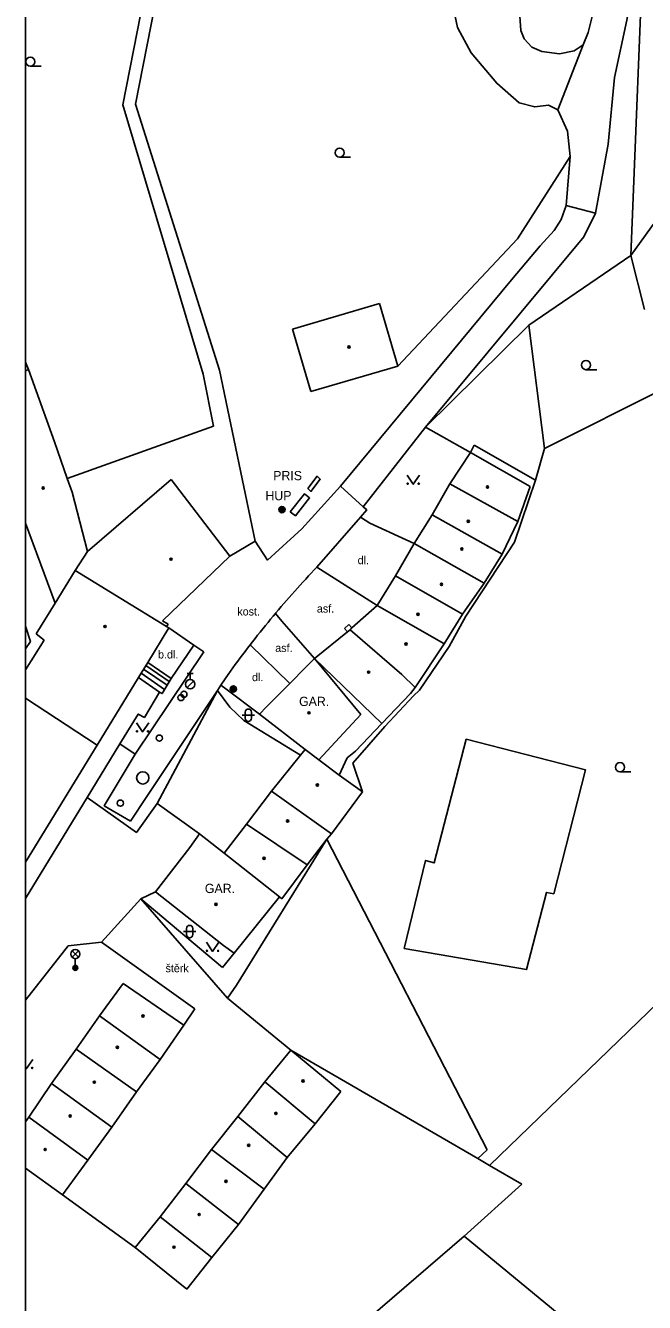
# Model space of a CAD drawing. Extents: x -598233 to -596890, y -1157848 to -1156431.
# Drawn here: x -598232.9 to -598182.6, y -1156791.2 to -1156687.5 of the extents above; entities that cross this region are included whole.
import ezdxf

# ---------------------------------------------------------------- set-up
doc = ezdxf.new("R2010")
doc.units = 0
for name, color, linetype in [('Level 10', 7, 'Continuous'), ('Level 11', 7, 'Continuous'), ('Level 24', 7, 'Continuous'), ('Level 25', 7, 'Continuous'), ('Level 27', 7, 'Continuous'), ('Level 28', 7, 'Continuous'), ('Level 33', 7, 'Continuous'), ('Level 36', 7, 'Continuous'), ('Level 39', 7, 'Continuous'), ('Level 40', 7, 'Continuous'), ('Level 41', 7, 'Continuous'), ('Level 5', 7, 'Continuous'), ('Level 51', 7, 'Continuous'), ('Level 8', 7, 'Continuous'), ('Vrstva 60', 7, 'Continuous'), ('zajmove_uzemi', 7, 'Continuous')]:
    doc.layers.add(name, color=color, linetype=linetype)

msp = doc.modelspace()

# ---------------------------------------------------------------- linework, layer by layer
at = {"layer": 'Level 10'}
for p, q in [((-598232.8901, -1156758.434), (-598227.88, -1156750.2199)), ((-598229.42, -1156762.27), (-598232.8901, -1156766.6794))]:
    msp.add_line(p, q, dxfattribs=at)
for points in [[(-598214.24, -1156729.4), (-598213.23, -1156730.95), (-598210.46, -1156728.4099), (-598207.31, -1156724.94)], [(-598205.46, -1156726.62), (-598207.31, -1156724.94)], [(-598209.23, -1156731.51), (-598205.7, -1156727.45), (-598205.18, -1156726.87), (-598205.46, -1156726.62)], [(-598209.69, -1156732), (-598209.91, -1156732.24), (-598210.14, -1156732.49)], [(-598209.69, -1156732), (-598209.46, -1156731.75), (-598209.23, -1156731.51)], [(-598216.69, -1156740.6), (-598216.44, -1156740.25), (-598216.25, -1156739.98), (-598216.05, -1156739.71), (-598215.86, -1156739.44), (-598215.66, -1156739.17), (-598215.46, -1156738.9), (-598215.26, -1156738.63), (-598215.06, -1156738.37), (-598214.86, -1156738.1), (-598214.65, -1156737.84), (-598214.45, -1156737.58), (-598214.24, -1156737.31), (-598214.04, -1156737.05), (-598213.83, -1156736.79), (-598213.62, -1156736.53), (-598213.41, -1156736.27), (-598213.2, -1156736.01), (-598212.99, -1156735.76), (-598212.77, -1156735.5), (-598212.6, -1156735.3), (-598212.56, -1156735.24), (-598212.35, -1156734.99), (-598212.13, -1156734.73), (-598211.91, -1156734.48), (-598211.69, -1156734.23), (-598211.48, -1156733.98), (-598211.26, -1156733.73), (-598211.03, -1156733.48), (-598210.81, -1156733.23), (-598210.59, -1156732.98), (-598210.37, -1156732.73), (-598210.14, -1156732.49)], [(-598218.42, -1156738.4), (-598223.98, -1156746.7), (-598225.23, -1156745.87)], [(-598217.29, -1156741.54), (-598217.02, -1156741.12), (-598216.69, -1156740.6)], [(-598223.04, -1156750.16), (-598217.29, -1156741.54)], [(-598227.88, -1156750.2199), (-598225.23, -1156745.87)], [(-598222.34, -1156757.89), (-598223.53, -1156758.46)], [(-598226.71, -1156761.9699), (-598223.53, -1156758.46)], [(-598229.42, -1156762.27), (-598226.71, -1156761.9699)]]:
    msp.add_lwpolyline(points, dxfattribs=at)
at = {"layer": 'Level 11'}
for p, q in [((-598232.8901, -1156736.323), (-598232.5, -1156737.55)), ((-598232.5, -1156737.55), (-598232.8901, -1156738.1619))]:
    msp.add_line(p, q, dxfattribs=at)
for points in [[(-598184.68, -1156671.86), (-598186.69, -1156686.03), (-598187.2, -1156688.09), (-598187.6, -1156689.09), (-598188.35, -1156689.6), (-598189.54, -1156689.84), (-598190.96, -1156689.65), (-598191.77, -1156689.29), (-598192.4, -1156688.61), (-598192.68, -1156687.94), (-598192.81, -1156685.99)], [(-598186.61, -1156702.76), (-598185.58, -1156697.18), (-598185.06, -1156691.75), (-598184.07, -1156687.1), (-598182.64, -1156678.57)], [(-598198.22, -1156685.76), (-598197.8, -1156687.7), (-598196.69, -1156689.76), (-598194.62, -1156692.22), (-598192.8, -1156693.81), (-598191.54, -1156694.15), (-598190.42, -1156694.01), (-598189.66, -1156694.37), (-598188.87, -1156696.11), (-598188.67, -1156698.18), (-598188.98, -1156702.16)], [(-598189.66, -1156694.37), (-598187.6, -1156689.09)], [(-598192.93, -1156704.87), (-598188.67, -1156698.18)], [(-598207.31, -1156724.94), (-598193.44, -1156708.18), (-598191.1, -1156705.43), (-598189.95, -1156704.17), (-598189.39, -1156703.28), (-598188.98, -1156702.16)], [(-598186.61, -1156702.76), (-598187.54, -1156704.69), (-598200.42, -1156720.14), (-598205.46, -1156726.62)], [(-598188.98, -1156702.16), (-598186.61, -1156702.76)], [(-598196.4699, -1156721.62), (-598196.75, -1156722.2)], [(-598191.4699, -1156724.45), (-598196.4699, -1156721.62)], [(-598191.4699, -1156724.45), (-598190.75, -1156721.89)], [(-598193.19, -1156729.48), (-598191.4699, -1156724.45)], [(-598205.7, -1156727.45), (-598204.93, -1156727.96)], [(-598201.33, -1156729.59), (-598204.93, -1156727.96)], [(-598197.14, -1156735.49), (-598193.19, -1156729.48)], [(-598204.33, -1156734.65), (-598209.23, -1156731.51)], [(-598212.07, -1156735.9), (-598212.6, -1156735.3)], [(-598209.43, -1156738.94), (-598212.07, -1156735.9)], [(-598198.49, -1156737.98), (-598197.14, -1156735.49)], [(-598221.26, -1156736.45), (-598219.2199, -1156737.85)], [(-598219.2199, -1156737.85), (-598221.07, -1156740.56)], [(-598219.2199, -1156737.85), (-598218.42, -1156738.4)], [(-598214.65, -1156737.84), (-598211.44, -1156740.97)], [(-598200.9099, -1156741.51), (-598198.49, -1156737.98)], [(-598222.9699, -1156739.26), (-598221.07, -1156740.56)], [(-598223.51, -1156740.14), (-598221.6, -1156741.45)], [(-598221.39, -1156741.1), (-598223.3, -1156739.8)], [(-598223.13, -1156739.52), (-598221.23, -1156740.82)], [(-598222, -1156741.67), (-598223.7199, -1156740.48)], [(-598221.07, -1156740.56), (-598221.8, -1156741.79), (-598222, -1156741.67)], [(-598216.63, -1156741.4), (-598217.02, -1156741.12)], [(-598217.29, -1156741.54), (-598222.19, -1156750.71), (-598223.88, -1156753.07), (-598227.88, -1156750.22)], [(-598222, -1156741.67), (-598223.24, -1156743.7199), (-598223.74, -1156743.45), (-598225.23, -1156745.87)], [(-598217.29, -1156741.54), (-598216.29, -1156742.89), (-598215.17, -1156743.9699), (-598210.57, -1156746.8)], [(-598213.89, -1156743.46), (-598216.63, -1156741.4)], [(-598203.7199, -1156744.46), (-598201.38, -1156741.98)], [(-598201.38, -1156741.98), (-598200.9099, -1156741.51)], [(-598206.32, -1156747.44), (-598203.7199, -1156744.46)], [(-598203.96, -1156744.23), (-598206.09, -1156746.46)], [(-598197.12, -1156745.48), (-598187.41, -1156747.99), (-598190, -1156758.05), (-598190.59, -1156757.94), (-598192.21, -1156764.21), (-598202.13, -1156762.49), (-598200.41, -1156755.34), (-598199.72, -1156755.54), (-598197.12, -1156745.48)], [(-598206.09, -1156746.46), (-598206.77, -1156747)], [(-598223.98, -1156746.7), (-598226.5, -1156750.9), (-598224.38, -1156752.16)], [(-598206.77, -1156747), (-598207.4099, -1156748.4099)], [(-598205.52, -1156749.76), (-598206.32, -1156747.44)], [(-598223.04, -1156750.16), (-598224.38, -1156752.16)], [(-598218.76, -1156753.17), (-598222.19, -1156750.71)], [(-598215.76, -1156765.48), (-598208.4099, -1156753.61)], [(-598223.53, -1156758.46), (-598216.89, -1156764.03)], [(-598216.48, -1156766.53), (-598223.53, -1156758.46)], [(-598226.71, -1156761.9699), (-598219.13, -1156767.4)], [(-598216.89, -1156764.03), (-598215.95, -1156762.86)], [(-598216.48, -1156766.53), (-598215.76, -1156765.48)], [(-598211.35, -1156770.76), (-598216.48, -1156766.53)], [(-598219.13, -1156767.4), (-598220.03, -1156768.71)], [(-598229.89, -1156782.5), (-598224, -1156786.77)]]:
    msp.add_lwpolyline(points, dxfattribs=at)
at = {"layer": 'Level 24'}
for points in [[(-598209.96, -1156725.13), (-598209.21, -1156724.14), (-598208.96, -1156724.39), (-598209.71, -1156725.37), (-598209.96, -1156725.13)], [(-598211.4, -1156727.02), (-598210.24, -1156725.58), (-598209.82, -1156725.9), (-598210.98, -1156727.35), (-598211.4, -1156727.02)], [(-598207, -1156736.5), (-598206.65, -1156736.17)], [(-598206.38, -1156736.46), (-598206.65, -1156736.17)], [(-598206.74, -1156736.77), (-598207, -1156736.5)]]:
    msp.add_lwpolyline(points, dxfattribs=at)
at = {"layer": 'Level 25'}
for centre, radius in [((-598212.07, -1156726.85), 0.25), ((-598212.07, -1156726.85), 0.2), ((-598212.07, -1156726.85), 0.15), ((-598212.07, -1156726.85), 0.1), ((-598212.07, -1156726.85), 0.05), ((-598216.01, -1156741.42), 0.25), ((-598216.01, -1156741.42), 0.2), ((-598216.01, -1156741.42), 0.15), ((-598216.01, -1156741.42), 0.1), ((-598216.01, -1156741.42), 0.05)]:
    msp.add_circle(centre, radius, dxfattribs=at)
at = {"layer": 'Level 27'}
msp.add_circle((-598223.37, -1156748.64), 0.5, dxfattribs=at)
at = {"layer": 'Level 28'}
for p, q in [((-598219.77, -1156740.155), (-598219.27, -1156740.155)), ((-598219.52, -1156740.655), (-598219.52, -1156740.155)), ((-598219.778, -1156741.302), (-598219.248, -1156740.772))]:
    msp.add_line(p, q, dxfattribs=at)
for centre, radius in [((-598219.52, -1156741.03), 0.375), ((-598220.27, -1156742.11), 0.25), ((-598220.03, -1156741.84), 0.25), ((-598222.02, -1156745.4099), 0.25), ((-598225.19, -1156750.69), 0.25)]:
    msp.add_circle(centre, radius, dxfattribs=at)
at = {"layer": 'Level 33'}
for p, q in [((-598229.115, -1156763.21), (-598228.585, -1156762.68)), ((-598229.115, -1156762.68), (-598228.585, -1156763.21)), ((-598228.85, -1156763.32), (-598228.85, -1156764.07))]:
    msp.add_line(p, q, dxfattribs=at)
for centre, radius in [((-598228.85, -1156762.945), 0.375), ((-598228.85, -1156764.07), 0.2), ((-598228.85, -1156764.07), 0.1445), ((-598228.85, -1156764.07), 0.0876)]:
    msp.add_circle(centre, radius, dxfattribs=at)
at = {"layer": 'Level 36'}
for p, q in [((-598232.5, -1156690.8449), (-598231.625, -1156690.8449)), ((-598207.38, -1156698.235), (-598206.505, -1156698.235)), ((-598187.38, -1156715.485), (-598186.505, -1156715.485)), ((-598215.046, -1156743.296), (-598215.046, -1156743.796)), ((-598214.546, -1156743.296), (-598214.546, -1156743.796)), ((-598215.296, -1156743.546), (-598214.296, -1156743.546)), ((-598184.62, -1156748.145), (-598183.745, -1156748.145)), ((-598219.806, -1156760.866), (-598219.806, -1156761.366)), ((-598219.306, -1156760.866), (-598219.306, -1156761.366)), ((-598220.056, -1156761.116), (-598219.056, -1156761.116))]:
    msp.add_line(p, q, dxfattribs=at)
for points in [[(-598201.91, -1156724.04), (-598201.41, -1156724.79), (-598200.91, -1156724.04)], [(-598223.89, -1156744.1599), (-598223.39, -1156744.9099), (-598222.89, -1156744.1599)], [(-598218.2, -1156761.98), (-598217.7, -1156762.73), (-598217.2, -1156761.98)], [(-598232.8901, -1156772.1149), (-598232.8, -1156772.25), (-598232.3, -1156771.5)]]:
    msp.add_lwpolyline(points, dxfattribs=at)
for centre, radius in [((-598232.5001, -1156690.4698), 0.375), ((-598207.3801, -1156697.8599), 0.375), ((-598187.3801, -1156715.1099), 0.375), ((-598201.8602, -1156724.7398), 0.05), ((-598200.9608, -1156724.7398), 0.05), ((-598223.8402, -1156744.8597), 0.05), ((-598222.9408, -1156744.8597), 0.05), ((-598184.6201, -1156747.7699), 0.375), ((-598218.1502, -1156762.6798), 0.05), ((-598217.2508, -1156762.6798), 0.05), ((-598232.3508, -1156772.1998), 0.05)]:
    msp.add_circle(centre, radius, dxfattribs=at)
for centre, start, end in [((-598214.7957, -1156743.2963), 0, 180), ((-598214.7957, -1156743.7963), 180, 0), ((-598219.5557, -1156760.8663), 0, 180), ((-598219.5557, -1156761.3663), 180, 0)]:
    msp.add_arc(centre, 0.25, start, end, dxfattribs=at)
at = {"layer": 'Level 39'}
for centre, radius in [((-598206.63, -1156713.64), 0.09), ((-598206.63, -1156713.64), 0.0398), ((-598231.46, -1156725.09), 0.09), ((-598231.46, -1156725.09), 0.0398), ((-598195.38, -1156725.01), 0.09), ((-598195.38, -1156725.01), 0.0398), ((-598196.94, -1156727.8), 0.09), ((-598196.94, -1156727.8), 0.0398), ((-598197.46, -1156730.05), 0.09), ((-598221.07, -1156730.87), 0.09), ((-598221.07, -1156730.87), 0.0398), ((-598197.46, -1156730.05), 0.0398), ((-598199.11, -1156732.92), 0.09), ((-598199.11, -1156732.92), 0.0398), ((-598201.02, -1156735.35), 0.09), ((-598201.02, -1156735.35), 0.0398), ((-598226.43, -1156736.34), 0.09), ((-598226.43, -1156736.34), 0.0398), ((-598201.99, -1156737.77), 0.09), ((-598201.99, -1156737.77), 0.0398), ((-598205.03, -1156740.05), 0.09), ((-598205.03, -1156740.05), 0.0398), ((-598209.87, -1156743.35), 0.09), ((-598209.87, -1156743.35), 0.0398), ((-598209.19, -1156749.2199), 0.09), ((-598209.19, -1156749.2199), 0.0398), ((-598211.61, -1156752.13), 0.09), ((-598211.61, -1156752.13), 0.0398), ((-598213.52, -1156755.17), 0.09), ((-598213.52, -1156755.17), 0.0398), ((-598217.43, -1156758.9099), 0.09), ((-598217.43, -1156758.9099), 0.0398), ((-598223.35, -1156767.98), 0.09), ((-598223.35, -1156767.98), 0.0398), ((-598225.43, -1156770.52), 0.09), ((-598225.43, -1156770.52), 0.0398), ((-598227.3, -1156773.35), 0.09), ((-598227.3, -1156773.35), 0.0398), ((-598210.35, -1156773.25), 0.09), ((-598210.35, -1156773.25), 0.0398), ((-598229.27, -1156776.1), 0.09), ((-598229.27, -1156776.1), 0.0398), ((-598212.56, -1156775.89), 0.09), ((-598212.56, -1156775.89), 0.0398), ((-598214.77, -1156778.48), 0.09), ((-598214.77, -1156778.48), 0.0398), ((-598231.3, -1156778.82), 0.09), ((-598231.3, -1156778.82), 0.0398), ((-598216.61, -1156781.4099), 0.09), ((-598216.61, -1156781.4099), 0.0398), ((-598218.79, -1156784.1), 0.09), ((-598218.79, -1156784.1), 0.0398), ((-598220.84, -1156786.75), 0.09), ((-598220.84, -1156786.75), 0.0398)]:
    msp.add_circle(centre, radius, dxfattribs=at)
at = {"layer": 'Level 5'}
for p, q in [((-598232.8901, -1156715.5829), (-598232.6599, -1156715.48)), ((-598232.8901, -1156727.9444), (-598230.48, -1156734.44)), ((-598232.8901, -1156739.8554), (-598231.38, -1156737.45)), ((-598232.8901, -1156742.151), (-598227.07, -1156745.98)), ((-598227.07, -1156745.98), (-598232.8901, -1156755.4825)), ((-598232.8901, -1156776.5748), (-598232.61, -1156776.18)), ((-598229.89, -1156782.5), (-598232.8901, -1156780.3427))]:
    msp.add_line(p, q, dxfattribs=at)
for points in [[(-598211.2199, -1156712.2), (-598204.14, -1156710.12)], [(-598204.14, -1156710.12), (-598202.65, -1156715.19)], [(-598209.73, -1156717.27), (-598211.2199, -1156712.2)], [(-598202.65, -1156715.19), (-598209.73, -1156717.27)], [(-598230.54, -1156721.35), (-598232.6599, -1156715.48)], [(-598229.5, -1156724.32), (-598230.54, -1156721.35)], [(-598198.43, -1156724.75), (-598196.75, -1156722.2)], [(-598196.75, -1156722.2), (-598191.9, -1156724.98)], [(-598229.11, -1156725.43), (-598229.5, -1156724.32)], [(-598227.86, -1156730.25), (-598221.07, -1156724.4)], [(-598221.07, -1156724.4), (-598216.3, -1156730.63)], [(-598199.88, -1156727.26), (-598198.43, -1156724.75)], [(-598198.43, -1156724.75), (-598192.9099, -1156727.81)], [(-598229.11, -1156725.43), (-598227.86, -1156730.25)], [(-598191.9, -1156724.98), (-598192.9099, -1156727.81)], [(-598201.33, -1156729.59), (-598199.88, -1156727.26)], [(-598199.88, -1156727.26), (-598194.19, -1156730.46)], [(-598192.9099, -1156727.81), (-598194.19, -1156730.46)], [(-598202.84, -1156732.24), (-598201.33, -1156729.59)], [(-598201.33, -1156729.59), (-598195.65, -1156732.81)], [(-598227.86, -1156730.25), (-598228.86, -1156731.8)], [(-598221.76, -1156735.88), (-598216.3, -1156730.63)], [(-598194.19, -1156730.46), (-598195.65, -1156732.81)], [(-598230.48, -1156734.44), (-598228.86, -1156731.8)], [(-598228.86, -1156731.8), (-598221.43, -1156736.34)], [(-598202.84, -1156732.24), (-598204.33, -1156734.65)], [(-598197.4, -1156735.33), (-598202.84, -1156732.24)], [(-598195.65, -1156732.81), (-598197.4, -1156735.33)], [(-598232.03, -1156736.94), (-598230.48, -1156734.44)], [(-598206.53, -1156736.6), (-598206.38, -1156736.46), (-598204.33, -1156734.65)], [(-598204.33, -1156734.65), (-598199.11, -1156737.62)], [(-598221.3, -1156736.1599), (-598221.76, -1156735.88)], [(-598221.3, -1156736.1599), (-598221.43, -1156736.34)], [(-598198.89, -1156737.75), (-598197.4, -1156735.33)], [(-598231.38, -1156737.45), (-598232.03, -1156736.94)], [(-598221.26, -1156736.45), (-598222.9699, -1156739.26)], [(-598221.43, -1156736.34), (-598221.26, -1156736.45)], [(-598209.43, -1156738.94), (-598206.74, -1156736.77), (-598206.53, -1156736.6)], [(-598206.53, -1156736.6), (-598202.34, -1156740.24)], [(-598198.89, -1156737.75), (-598201.24, -1156741.29)], [(-598199.11, -1156737.62), (-598198.89, -1156737.75)], [(-598222.9699, -1156739.26), (-598223.7199, -1156740.48)], [(-598210.12, -1156739.64), (-598209.43, -1156738.94)], [(-598203.96, -1156744.23), (-598209.43, -1156738.94)], [(-598209.43, -1156738.94), (-598205.6599, -1156743.49)], [(-598211.9699, -1156741.51), (-598211.44, -1156740.97), (-598210.12, -1156739.64)], [(-598202.34, -1156740.24), (-598201.24, -1156741.29)], [(-598223.7199, -1156740.48), (-598227.07, -1156745.98)], [(-598201.24, -1156741.29), (-598201.63, -1156741.79)], [(-598213.31, -1156742.87), (-598211.9699, -1156741.51)], [(-598201.63, -1156741.79), (-598203.96, -1156744.23)], [(-598213.89, -1156743.46), (-598213.31, -1156742.87)], [(-598210.19, -1156746.33), (-598213.89, -1156743.46)], [(-598205.6599, -1156743.49), (-598207.39, -1156745.36)], [(-598207.39, -1156745.36), (-598209.06, -1156747.17)], [(-598210.57, -1156746.8), (-598210.19, -1156746.33)], [(-598210.19, -1156746.33), (-598209.06, -1156747.17)], [(-598212.93, -1156749.71), (-598210.57, -1156746.8)], [(-598209.06, -1156747.17), (-598207.4099, -1156748.4099)], [(-598207.4099, -1156748.4099), (-598205.52, -1156749.76)], [(-598214.95, -1156752.39), (-598212.93, -1156749.71)], [(-598208.05, -1156753.18), (-598212.93, -1156749.71)], [(-598205.52, -1156749.76), (-598208.05, -1156753.18)], [(-598216.77, -1156754.75), (-598214.95, -1156752.39)], [(-598210.02, -1156755.69), (-598214.95, -1156752.39)], [(-598218.76, -1156753.17), (-598219.56, -1156754.28)], [(-598216.77, -1156754.75), (-598218.76, -1156753.17)], [(-598208.4099, -1156753.61), (-598210.02, -1156755.69)], [(-598208.05, -1156753.18), (-598208.4099, -1156753.61)], [(-598219.56, -1156754.28), (-598222.34, -1156757.89)], [(-598212.26, -1156758.31), (-598216.77, -1156754.75)], [(-598210.02, -1156755.69), (-598212.08, -1156758.45)], [(-598222.34, -1156757.89), (-598216.81, -1156762.24)], [(-598212.26, -1156758.31), (-598215.95, -1156762.86)], [(-598212.08, -1156758.45), (-598212.26, -1156758.31)], [(-598215.95, -1156762.86), (-598216.81, -1156762.24)], [(-598226.89, -1156767.96), (-598224.9699, -1156765.33)], [(-598224.9699, -1156765.33), (-598220.03, -1156768.71)], [(-598228.79, -1156770.6599), (-598226.89, -1156767.96)], [(-598221.9699, -1156771.51), (-598226.89, -1156767.96)], [(-598220.03, -1156768.71), (-598221.9699, -1156771.51)], [(-598230.78, -1156773.4699), (-598228.79, -1156770.6599)], [(-598223.87, -1156774.13), (-598228.79, -1156770.6599)], [(-598213.4699, -1156773.32), (-598211.35, -1156770.76)], [(-598211.35, -1156770.76), (-598207.29, -1156774.1)], [(-598221.9699, -1156771.51), (-598223.87, -1156774.13)], [(-598232.61, -1156776.18), (-598230.78, -1156773.4699)], [(-598225.89, -1156777), (-598230.78, -1156773.4699)], [(-598215.65, -1156776.15), (-598213.4699, -1156773.32)], [(-598209.37, -1156776.7199), (-598213.4699, -1156773.32)], [(-598223.87, -1156774.13), (-598225.89, -1156777)], [(-598207.29, -1156774.1), (-598209.37, -1156776.7199)], [(-598227.84, -1156779.69), (-598232.61, -1156776.18)], [(-598217.8, -1156778.82), (-598215.65, -1156776.15)], [(-598211.65, -1156779.4699), (-598215.65, -1156776.15)], [(-598225.89, -1156777), (-598227.84, -1156779.69)], [(-598209.37, -1156776.7199), (-598211.65, -1156779.4699)], [(-598227.84, -1156779.69), (-598229.89, -1156782.5)], [(-598219.86, -1156781.58), (-598217.8, -1156778.82)], [(-598213.51, -1156782.03), (-598217.8, -1156778.82)], [(-598211.65, -1156779.4699), (-598213.51, -1156782.03)], [(-598221.9699, -1156784.28), (-598219.86, -1156781.58)], [(-598215.6, -1156784.9099), (-598219.86, -1156781.58)], [(-598213.51, -1156782.03), (-598215.6, -1156784.9099)], [(-598224, -1156786.77), (-598221.9699, -1156784.28)], [(-598217.76, -1156787.6), (-598221.9699, -1156784.28)], [(-598215.6, -1156784.9099), (-598217.76, -1156787.6)], [(-598219.8, -1156790.1599), (-598224, -1156786.77)], [(-598217.76, -1156787.6), (-598219.8, -1156790.1599)]]:
    msp.add_lwpolyline(points, dxfattribs=at)
at = {"layer": 'Level 51'}
msp.add_line((-598232.6599, -1156715.48), (-598232.8901, -1156714.8773), dxfattribs=at)
for points in [[(-598225, -1156693.9699), (-598221.19, -1156674.65)], [(-598220.5, -1156676.28), (-598223.9699, -1156693.9099)], [(-598183.75, -1156706.2), (-598182.64, -1156678.57)], [(-598218.46, -1156715.86), (-598225, -1156693.9699)], [(-598223.9699, -1156693.9099), (-598217.14, -1156715.53)], [(-598183.75, -1156706.2), (-598175.89, -1156695.32)], [(-598192.93, -1156704.87), (-598202.65, -1156715.19)], [(-598192.03, -1156711.87), (-598183.75, -1156706.2)], [(-598182.62, -1156710.61), (-598183.75, -1156706.2)], [(-598192.03, -1156711.87), (-598200.42, -1156720.14)], [(-598190.75, -1156721.89), (-598192.03, -1156711.87)], [(-598217.64, -1156720.08), (-598218.46, -1156715.86)], [(-598217.14, -1156715.53), (-598214.24, -1156729.4)], [(-598190.75, -1156721.89), (-598180.9099, -1156716.95)], [(-598229.5, -1156724.32), (-598217.64, -1156720.08)], [(-598200.42, -1156720.14), (-598196.75, -1156722.2)], [(-598208.4099, -1156753.61), (-598195.39, -1156778.85)], [(-598195.2199, -1156780.11), (-598177.49, -1156762.98)], [(-598211.35, -1156770.76), (-598196.1599, -1156779.56)], [(-598195.39, -1156778.85), (-598196.1599, -1156779.56)], [(-598196.1599, -1156779.56), (-598195.2199, -1156780.11)], [(-598192.6, -1156781.63), (-598195.2199, -1156780.11)], [(-598197.28, -1156785.85), (-598192.6, -1156781.63)], [(-598214.99, -1156801.12), (-598197.28, -1156785.85)], [(-598197.28, -1156785.85), (-598185.08, -1156795.9)]]:
    msp.add_lwpolyline(points, dxfattribs=at)
at = {"layer": 'Level 8'}
msp.add_lwpolyline([(-598216.3, -1156730.63), (-598214.24, -1156729.4)], dxfattribs=at)
at = {"layer": 'Vrstva 60'}
msp.add_lwpolyline([(-598232.8901, -1156430.8558), (-598232.8901, -1157835.5817)], dxfattribs=at)
at = {"layer": 'zajmove_uzemi'}
msp.add_lwpolyline([(-598232.8901, -1156430.8558), (-596890.4624, -1156430.8558), (-596890.4624, -1157848.4611), (-598232.8901, -1157848.4611)], close=True, dxfattribs=at)

# ---------------------------------------------------------------- texts
at = {"layer": 'Level 40'}
for s, p in [('dl.', (-598205.92, -1156731.28)), ('kost.', (-598215.69, -1156735.45)), ('asf.', (-598209.23, -1156735.21)), ('b.dl.', (-598222.13, -1156738.94)), ('asf.', (-598212.61, -1156738.41)), ('dl.', (-598214.5, -1156740.78)), ('štěrk', (-598221.52, -1156764.42))]:
    msp.add_text(s, height=0.65, dxfattribs=at).set_placement(p)
at = {"layer": 'Level 41'}
for s, p in [('PRIS', (-598212.78, -1156724.46)), ('HUP', (-598213.41, -1156726.09)), ('GAR.', (-598210.68, -1156742.8)), ('GAR.', (-598218.33, -1156757.99))]:
    msp.add_text(s, height=0.75, dxfattribs=at).set_placement(p)

doc.saveas('drawing.dxf')
